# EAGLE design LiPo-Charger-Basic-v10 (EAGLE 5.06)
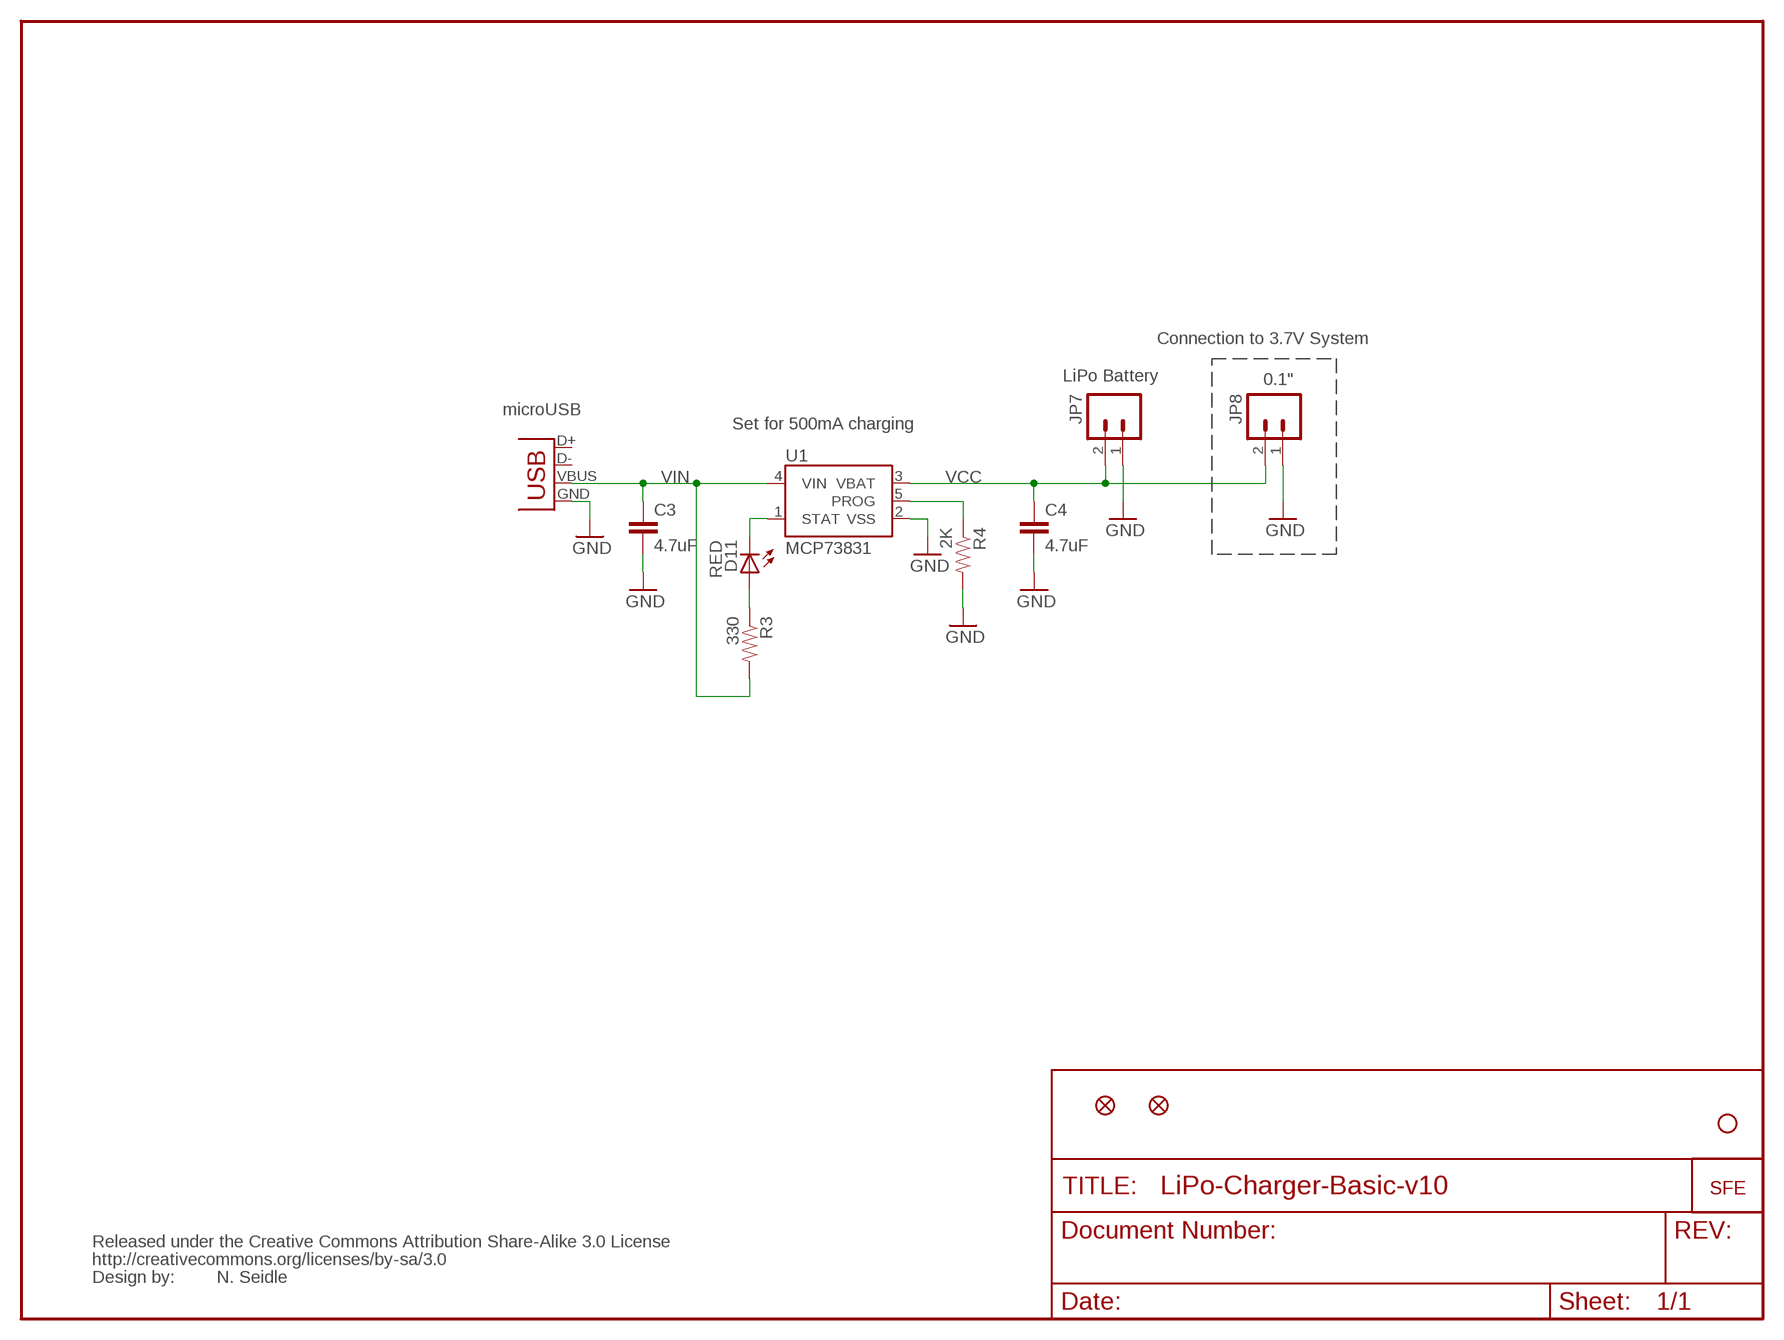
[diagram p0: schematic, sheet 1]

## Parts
C3  4.7uF  CAP0402-CAP  [0402-CAP]
C4  4.7uF  CAP0402-CAP  [0402-CAP]
D11  RED  LED0603  [LED-0603]
JP1  LOGO-SFESK  [SFE-LOGO-FLAME]
JP2  STAND-OFF  [STAND-OFF]
JP3  FIDUCIAL1X2  [FIDUCIAL-1X2]
JP4  FIDUCIAL1X2  [FIDUCIAL-1X2]
JP7  LiPo Battery  M02-JST-2MM-SMT  [JST-2-SMD]
JP8  M02PTH  [1X02]
R3  330  RESISTOR0402-RES  [0402-RES]
R4  2K  RESISTOR0402-RES  [0402-RES]
U1  MCP73831  [SOT23-5]
U$1  CREATIVE_COMMONS  [CREATIVE_COMMONS]
X1  Micro USB  USB-MICROB  [USB-MICROB]

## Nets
GND: C3.2 C4.2 JP7.1 JP8.1 R4.2 U1.2(VSS) X1.GND
N$3: D11.A R3.1
PROG: R4.1 U1.5(PROG)
STAT: D11.C U1.1(STAT)
VCC: C4.1 JP7.2 JP8.2 U1.3(VBAT)
VIN: C3.1 R3.2 U1.4(VIN) X1.VBUS
Unconnected: X1.D+ X1.D-

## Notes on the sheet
- Connection to 3.7V System
- 0.1"
- microUSB
- Set for 500mA charging
- N. Seidle

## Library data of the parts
C3 C4 = SparkFun:CAP: Capacitor
D11 = SparkFun:LED: LEDs
JP1 = SparkFun:LOGO-SFE: Spark Fun Electronics PCB Logo
JP2 = SparkFun:STAND-OFF: Stand Off
JP3 JP4 = SparkFun:FIDUCIAL: Fiducial Alignment Points
JP7 JP8 = SparkFun:M02: Header 2
R3 R4 = SparkFun:RESISTOR: Resistor
U1 = SparkFun:MCP73831: Microchip's MCP73831 Miniature single cell, fully integrated Li-Ion, Li-polymer charge management controller http://ww1.microchip.com/downloads/en/DeviceDoc/21984a.pdf
U$1 = SparkFun:CREATIVE_COMMONS
X1 = SparkFun:USB: USB Connectors USB-B-PTH is fully proven SKU : PRT-00139 USB-miniB is fully proven SKU : PRT-00587 USB-A-PCB is untested. USB-A-H is throughly reviewed, but untested. Spark Fun Electronics SKU : PRT-00437 USB-B-SMT is throughly reviewed, but untested. Needs silkscreen touching up. USB-A-S has not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

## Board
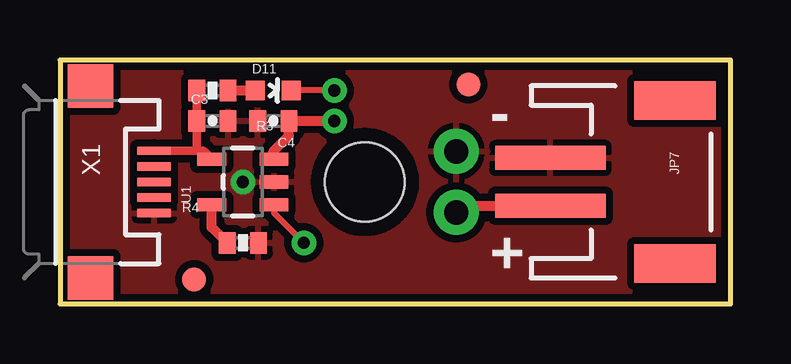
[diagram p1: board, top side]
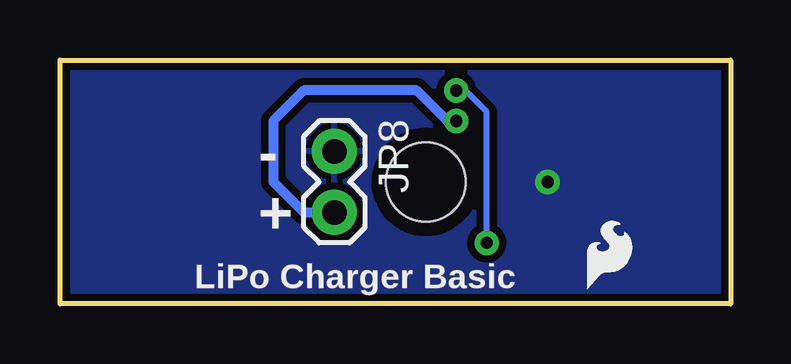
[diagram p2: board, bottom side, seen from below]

Size 27.94 x 10.16 mm. Coordinates in mm from the lower left corner, seen from the top.
Outline: 27.94,0 27.94,10.16 0,10.16 0,0 27.94,0
Copper layers (1*16): Top 0.035mm / dielectric 1.5mm / Bottom 0.035mm
Design rules "SparkFun": minimum track width 8mil, minimum drill 20mil, track to track 8mil, track to pad 8mil, pad to pad 8mil, via to via 8mil, smd to smd 6mil, copper to edge 8mil, drill to drill 8mil, minimum pad ring 12mil, minimum via ring 10mil, stop-mask expansion 4mil, vias tented up to drill 25mil, thermal gap 10mil

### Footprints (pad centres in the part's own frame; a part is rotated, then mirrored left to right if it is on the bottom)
0402-CAP = smd 0.7 x 0.9: 1 -0.65,0; 2 0.65,0
LED-0603 = smd 0.8 x 0.8: A 0,-0.75; C 0,0.75
STAND-OFF = hole 3.302: 0,0
FIDUCIAL-1X2 = smd 1 x 1: 1 0,0
JST-2-SMD = smd 1 x 4.6: 1 -1,-3.7; 2 1,-3.7 | smd 1.6 x 3.4: NC1 -3.4,1.5; NC2 3.4,1.5
1X02 = drill 1.016 pad 1.88 round: 1 0,0; 2 2.54,0
0402-RES = smd 0.7 x 0.9: 1 -0.65,0; 2 0.65,0
SOT23-5 = smd 0.55 x 1.2: 1 -0.95,-1.3; 2 0,-1.3; 3 0.95,-1.3; 4 0.95,1.3; 5 -0.95,1.3
USB-MICROB = smd 0.35 x 1.4: D+ 0,2.65; D- -0.65,2.65; GND 1.3,2.65; ID 0.65,2.65; VBUS -1.3,2.65 | smd 1.8 x 1.9: MT1 -4,0; MT2 4,0

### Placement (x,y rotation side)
C3  6.35,7.62 0 top
C4  8.89,7.62 180 top
D11  8.89,8.89 270 top
JP1  5.97,0.64 0 bottom
JP2  12.7,5.08 0 top
JP3  5.59,1.02 0 top
JP4  17.02,9.14 0 top
JP7  24.13,5.08 270 top
JP8  16.51,6.35 270 bottom
R3  6.35,8.89 180 top
R4  7.62,2.54 0 top
U1  7.62,5.08 90 top
U$1  not placed on the board
X1  1.27,5.08 270 top

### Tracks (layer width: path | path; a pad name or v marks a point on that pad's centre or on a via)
GND  (via drill 0.51)
  other vias: 7.62,5.08
  pour Bottom (isolate 0.305): 0,0 0,10.16 27.94,10.16 27.94,0
  pour Top (isolate 0.305): 0,10.16 27.94,10.16 27.94,0 0,0
N$3
  Top 0.406: R3.1 D11.A
PROG
  Top 0.406: U1.5 6.32,3.19 R4.1
STAT  (via drill 0.51)
  Top 0.254: v11.43,8.89 D11.C | U1.1 8.92,3.78 v10.16,2.54
  Bottom 0.254: v11.43,8.89 11.05,8.89 10.16,8 v10.16,2.54
VCC  (via drill 0.51)
  Top 0.406: v11.43,7.62 C4.1 9.54,7 8.89,6.35 8.89,6.06 U1.3 | JP7.2 16.78,4.08 JP8.2
  Bottom 0.406: JP8.2 17.78,3.81 19.05,5.08 19.05,7.62 17.78,8.89 13.08,8.89 11.81,7.62 v11.43,7.62
VIN
  Top 0.356: X1.VBUS 5.71,6.38 | 5.71,6.38 5.97,6.38 U1.4 | 5.71,6.38 5.7,6.39 C3.1 R3.2

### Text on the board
tPlace: - | + | N. Seidle
bPlace: - | + | LiPo Charger Basic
